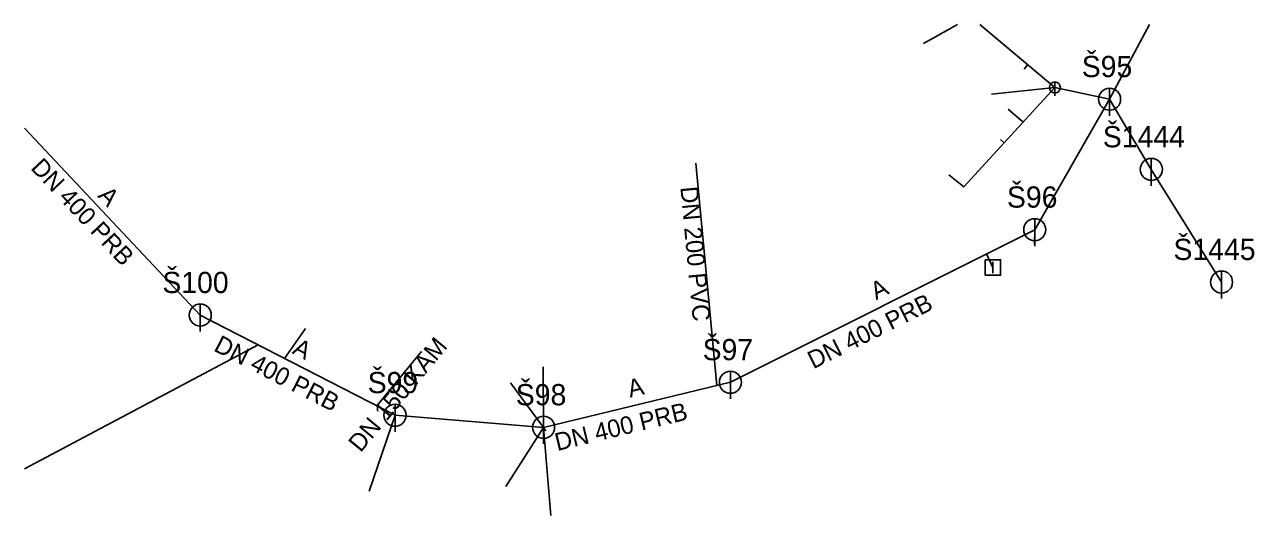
# Model space of a CAD drawing. Extents: x -483822 to -483711, y -1128563 to -1128518.
import ezdxf

# ---------------------------------------------------------------- set-up
doc = ezdxf.new("R2010")
doc.units = 0
for name, color, linetype in [('_pripojka_kanal_destova_priblizne_', 7, 'Continuous'), ('_pripojka_kanal_jednotna_priblizne_', 7, 'Continuous'), ('_stoka_jednotna_smvak_prevzato_z_dokumentace_', 7, 'Continuous'), ('Default', 7, 'Continuous'), ('MoLevel 119', 7, 'Continuous'), ('MoLevel 120', 7, 'Continuous'), ('MoLevel 124', 7, 'Continuous'), ('MoLevel 57', 7, 'Continuous'), ('MoLevel 63', 7, 'Continuous'), ('MoLevel 68', 7, 'Continuous'), ('MoLevel 69', 7, 'Continuous')]:
    doc.layers.add(name, color=color, linetype=linetype)

# ---------------------------------------------------------------- blocks, each defined once
blk = doc.blocks.new('_vpust_')
at = {"layer": 'Default'}
blk.add_line((0, 0.000025), (0, -0.000025), dxfattribs=at)
blk.add_lwpolyline([(-0.000035, 0.000035), (0.000035, 0.000035), (0.000035, -0.000035), (-0.000035, -0.000035), (-0.000035, 0.000035)], dxfattribs=at)
blk = doc.blocks.new('_sachta_kanal_prip_')
at = {"layer": 'Default'}
blk.add_line((0, 0.00005), (0, -0.000075), dxfattribs=at)
blk.add_circle((0, 0), 0.00005, dxfattribs=at)
blk = doc.blocks.new('_sachta_kanal_prevzato_z_dokumentace_')
at = {"layer": 'Default'}
blk.add_line((0, 0.00005), (0, -0.000075), dxfattribs=at)
blk.add_circle((0, 0), 0.00005, dxfattribs=at)

msp = doc.modelspace()

# ---------------------------------------------------------------- linework, layer by layer
at = {"layer": '_pripojka_kanal_destova_priblizne_'}
for p, q in [((-483740.52, -1128520.07), (-483737.46, -1128518.34)), ((-483735.41, -1128518.34), (-483728.61, -1128524.05)), ((-483731.41, -1128522.4), (-483731.08, -1128521.98)), ((-483732.84, -1128526.03), (-483731.5, -1128527.2)), ((-483733.54, -1128528.76), (-483733.21, -1128529.06)), ((-483730.46, -1128538.26), (-483730.44, -1128536.95)), ((-483734.23, -1128540.38), (-483734.8, -1128539.14)), ((-483774.8, -1128555.2), (-483775, -1128554.88))]:
    msp.add_line(p, q, dxfattribs=at)
msp.add_lwpolyline([(-483738.22, -1128531.96), (-483736.88, -1128533.06), (-483728.61, -1128524.05)], dxfattribs=at)
at = {"layer": '_pripojka_kanal_jednotna_priblizne_'}
for p, q in [((-483734.35, -1128524.66), (-483728.61, -1128524.05)), ((-483728.61, -1128524.05), (-483723.65, -1128525.11)), ((-483761.18, -1128530.91), (-483759.29, -1128551.09)), ((-483796.6, -1128545.91), (-483798.5, -1128548.63)), ((-483822.09, -1128558.65), (-483800.91, -1128547.39)), ((-483786.08, -1128548), (-483790.14, -1128552.93)), ((-483775.04, -1128549.4), (-483775, -1128554.88)), ((-483778, -1128550.85), (-483775, -1128554.88)), ((-483790.82, -1128560.68), (-483788.48, -1128553.78)), ((-483778.41, -1128560.25), (-483775, -1128554.88)), ((-483774.34, -1128562.87), (-483775, -1128554.88))]:
    msp.add_line(p, q, dxfattribs=at)
at = {"layer": '_stoka_jednotna_smvak_prevzato_z_dokumentace_'}
for p, q in [((-483723.65, -1128525.11), (-483720.02, -1128518.34)), ((-483730.44, -1128536.95), (-483723.65, -1128525.11)), ((-483719.86, -1128531.48), (-483723.65, -1128525.11)), ((-483822.09, -1128527.74), (-483806.15, -1128544.7)), ((-483713.49, -1128541.7), (-483719.86, -1128531.48)), ((-483758.05, -1128550.79), (-483730.44, -1128536.95)), ((-483806.15, -1128544.7), (-483788.48, -1128553.78)), ((-483775, -1128554.88), (-483758.05, -1128550.79)), ((-483788.48, -1128553.78), (-483775, -1128554.88))]:
    msp.add_line(p, q, dxfattribs=at)

# ---------------------------------------------------------------- block references
at = {"layer": 'MoLevel 119', "xscale": 20000, "yscale": 20000}
for p in [(-483723.65, -1128525.11), (-483719.86, -1128531.48), (-483730.44, -1128536.95), (-483713.49, -1128541.7), (-483806.15, -1128544.7), (-483758.05, -1128550.79), (-483788.48, -1128553.78), (-483775, -1128554.88)]:
    msp.add_blockref('_sachta_kanal_prevzato_z_dokumentace_', p, dxfattribs=at)
at = {"layer": 'MoLevel 57', "xscale": 10000, "yscale": 10000}
msp.add_blockref('_sachta_kanal_prip_', (-483728.61, -1128524.05), dxfattribs=at)
at = {"layer": 'MoLevel 63', "xscale": 20000, "yscale": 20000}
msp.add_blockref('_vpust_', (-483734.23, -1128540.38), dxfattribs=at)

# ---------------------------------------------------------------- texts
at = {"layer": 'MoLevel 120'}
for s, p in [('Š95', (-483726.17, -1128523.11)), ('Š1444', (-483724.26, -1128529.48)), ('Š96', (-483732.96, -1128534.95)), ('Š1445', (-483717.85, -1128539.7)), ('Š100', (-483809.59, -1128542.7)), ('Š97', (-483760.57, -1128548.79)), ('Š99', (-483790.96, -1128551.78)), ('Š98', (-483777.52, -1128552.88))]:
    msp.add_text(s, height=1.926, dxfattribs=at).set_placement(p)
at = {"layer": 'MoLevel 124'}
for s, rotation, p in [('DN 200 PVC', 275.3391, (-483762.59, -1128533.09)), ('DN 150 KAM', 50.5099, (-483791.6, -1128557.23))]:
    msp.add_text(s, height=1.605, rotation=rotation, dxfattribs=at).set_placement(p)
at = {"layer": 'MoLevel 68'}
for rotation, p in [(313.2276, (-483821.61, -1128531.4)), (26.6231, (-483750.53, -1128549.62)), (332.8029, (-483805.02, -1128547.89)), (13.5644, (-483773.76, -1128557.03))]:
    msp.add_text('DN 400 PRB', height=1.605, rotation=rotation, dxfattribs=at).set_placement(p)
at = {"layer": 'MoLevel 69'}
for rotation, p in [(313.2276, (-483815.52, -1128533.93)), (26.6231, (-483744.83, -1128543.36)), (332.8029, (-483797.89, -1128548.14)), (13.5644, (-483767.16, -1128552.19))]:
    msp.add_text('A', height=1.6, rotation=rotation, dxfattribs=at).set_placement(p)

doc.saveas('drawing.dxf')
